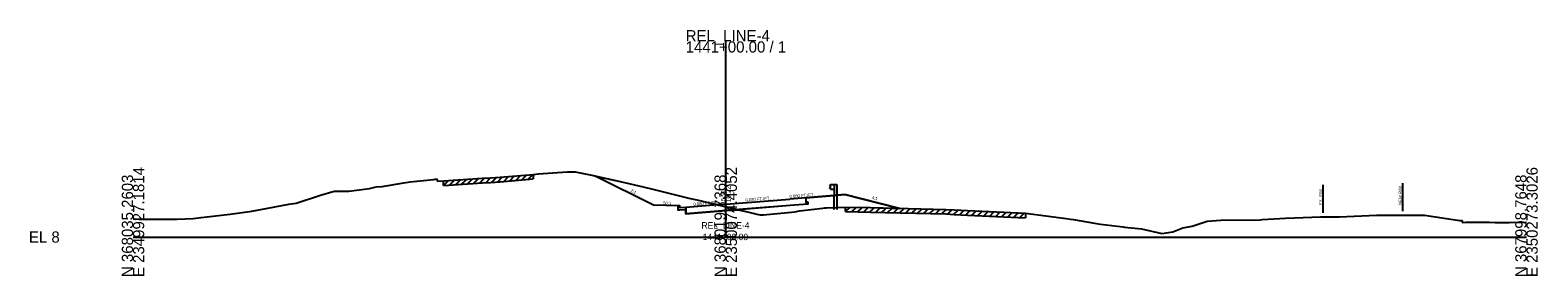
# Model space of a CAD drawing. Extents: x -26 to 2350146, y -10 to 368200.
# Drawn here: x 1974.3 to 2350.9, y 1990.3 to 2051.7 of the extents above; entities that cross this region are included whole.
import ezdxf

# ---------------------------------------------------------------- set-up
doc = ezdxf.new("R2010")
doc.units = 0
for name, color, linetype in [('RD_GPK_XS_Cell', 7, 'Continuous'), ('RD_XS_Base', 7, 'Continuous'), ('RD_XS_CurbBase', 7, 'Continuous'), ('RD_XS_CurbFront', 7, 'Continuous'), ('RD_XS_CurbTop', 7, 'Continuous'), ('RD_XS_Ditch', 7, 'Continuous'), ('RD_XS_EarthShd', 7, 'Continuous'), ('RD_XS_EwShp', 7, 'Continuous'), ('RD_XS_ExGround', 7, 'Continuous'), ('RD_XS_ExPaveRet', 7, 'Continuous'), ('RD_XS_ExRW', 7, 'Continuous'), ('RD_XS_GR', 7, 'Continuous'), ('RD_XS_NewRW', 7, 'Continuous'), ('RD_XS_Pave', 7, 'Continuous'), ('RD_XS_PaveShd', 7, 'Continuous'), ('RD_XS_TieSlope', 7, 'Continuous'), ('RD_XS_TX_Elev_EX', 7, 'Continuous'), ('RD_XS_TX_Elev_PR', 7, 'Continuous'), ('RD_XS_TX_Slope', 7, 'Continuous'), ('RD_XS_TX_Station', 7, 'Continuous'), ('RD_XS_TX_TOC', 7, 'Continuous')]:
    doc.layers.add(name, color=color, linetype=linetype)

msp = doc.modelspace()

# ---------------------------------------------------------------- linework, layer by layer
at = {"layer": 'RD_GPK_XS_Cell'}
for p, q in [((2148.04, 2000), (2148.04, 2048.88)), ((2000, 2000), (2148.04, 2000)), ((2148.04, 2000), (2348.04, 2000))]:
    msp.add_line(p, q, dxfattribs=at)
at = {"layer": 'RD_XS_Base'}
for p, q in [((2164.17, 2007.87), (2148.17, 2006.59)), ((2168.55, 2008.22), (2164.17, 2007.87)), ((2168.05, 2009.82), (2168.05, 2008.68)), ((2168.55, 2008.72), (2168.55, 2008.22)), ((2138.04, 2005.78), (2138.04, 2006.9)), ((2148.17, 2006.59), (2138.04, 2005.78))]:
    msp.add_line(p, q, dxfattribs=at)
at = {"layer": 'RD_XS_CurbBase'}
for p, q in [((2136.04, 2007.82), (2136.04, 2006.82)), ((2168.55, 2008.72), (2168.05, 2008.68)), ((2136.04, 2006.82), (2136.54, 2006.82)), ((2136.54, 2006.82), (2138.04, 2006.9))]:
    msp.add_line(p, q, dxfattribs=at)
at = {"layer": 'RD_XS_CurbFront'}
msp.add_line((2138.04, 2006.9), (2138.04, 2007.4), dxfattribs=at)
at = {"layer": 'RD_XS_CurbTop'}
for p, q in [((2136.54, 2007.82), (2136.04, 2007.82)), ((2136.62, 2007.32), (2136.54, 2007.82)), ((2138.04, 2007.4), (2136.62, 2007.32)), ((2138.04, 2007.42), (2138.04, 2007.4))]:
    msp.add_line(p, q, dxfattribs=at)
at = {"layer": 'RD_XS_Ditch'}
msp.add_line((2177.79, 2010.6), (2191.5, 2007.17), dxfattribs=at)
at = {"layer": 'RD_XS_EarthShd'}
for p, q in [((2136.04, 2007.82), (2130.04, 2007.94)), ((2168.05, 2009.82), (2174.04, 2010.3))]:
    msp.add_line(p, q, dxfattribs=at)
at = {"layer": 'RD_XS_EwShp'}
for points in [[(2145.92, 2008.05), (2138.04, 2007.4), (2136.62, 2007.32), (2136.54, 2007.82), (2136.04, 2007.82), (2130.04, 2007.94), (2115.42, 2015.24), (2121.65, 2013.9), (2127.43, 2012.5), (2130.13, 2011.9), (2134.8, 2010.67), (2138.79, 2009.71), (2141.53, 2009.1), (2145.31, 2008.19)], [(2138.04, 2007.4), (2136.62, 2007.32), (2136.54, 2007.82), (2136.04, 2007.82), (2136.04, 2006.82), (2136.54, 2006.82), (2138.04, 2006.9)], [(2145.92, 2008.05), (2138.04, 2007.4), (2138.04, 2006.9), (2138.04, 2005.78), (2148.17, 2006.59), (2151.14, 2006.83), (2148.04, 2007.55)], [(2151.14, 2006.83), (2153.45, 2006.29), (2155.79, 2005.7), (2156.65, 2005.52), (2157.47, 2005.52), (2165.32, 2006.32), (2166.44, 2006.51), (2172.26, 2007.21), (2172.79, 2007.29), (2173.2, 2007.3), (2177.97, 2007.49), (2184.18, 2007.34), (2191.5, 2007.17), (2177.79, 2010.6), (2174.04, 2010.3), (2168.05, 2009.82), (2168.05, 2008.68), (2168.55, 2008.72), (2168.55, 2008.22), (2164.17, 2007.87)]]:
    msp.add_lwpolyline(points, close=True, dxfattribs=at)
at = {"layer": 'RD_XS_ExGround'}
msp.add_lwpolyline([(2000, 2004.54), (2001.45, 2004.5), (2002.57, 2004.5), (2010.99, 2004.48), (2015.02, 2004.6), (2016.98, 2004.87), (2023.54, 2005.63), (2024.25, 2005.7), (2029.69, 2006.5), (2035.02, 2007.47), (2038.95, 2008.19), (2040.77, 2008.48), (2046.8, 2010.43), (2050.28, 2011.44), (2053.94, 2011.45), (2059.04, 2012.16), (2060.75, 2012.51), (2062.2, 2012.66), (2067.63, 2013.53), (2069.2, 2013.78), (2075.05, 2014.39), (2075.42, 2014.42), (2075.92, 2014.42), (2076.08, 2013.93), (2077.58, 2014.01), (2087.32, 2014.67), (2089.26, 2014.8), (2091.68, 2014.98), (2099.91, 2015.65), (2101.24, 2015.82), (2108.44, 2016.29), (2110.41, 2016.27), (2114.58, 2015.43), (2121.65, 2013.9), (2127.43, 2012.5), (2130.13, 2011.9), (2134.8, 2010.67), (2138.79, 2009.71), (2141.53, 2009.1), (2145.31, 2008.19), (2148.04, 2007.55), (2153.45, 2006.29), (2155.79, 2005.7), (2156.65, 2005.52), (2157.47, 2005.52), (2165.32, 2006.32), (2166.44, 2006.51), (2172.26, 2007.21), (2172.79, 2007.29), (2173.2, 2007.3), (2177.97, 2007.49), (2184.18, 2007.34), (2203.02, 2006.91), (2205.09, 2006.8), (2208.44, 2006.64), (2222.92, 2005.97), (2233.11, 2004.64), (2234.19, 2004.5), (2234.92, 2004.4), (2240.13, 2003.47), (2241.64, 2003.24), (2247.3, 2002.53), (2247.67, 2002.5), (2251.85, 2002.07), (2256.93, 2000.92), (2259.67, 2001.33), (2262.21, 2002.33), (2264.52, 2002.71), (2268.28, 2003.98), (2271.69, 2004.2), (2281.55, 2004.3), (2282.04, 2004.36), (2287.85, 2004.73), (2290.08, 2004.77), (2296.63, 2005.07), (2301.33, 2005.05), (2310.62, 2005.48), (2312.02, 2005.44), (2314.31, 2005.45), (2322.53, 2005.44), (2330.81, 2004.25), (2331.34, 2004.12), (2331.88, 2004.12), (2332.05, 2003.62), (2332.87, 2003.7), (2335.31, 2003.7), (2336.95, 2003.69), (2338.81, 2003.68), (2340.2, 2003.67), (2343.69, 2003.63), (2348.04, 2003.75)], dxfattribs=at)
at = {"layer": 'RD_XS_ExPaveRet'}
for p, q in [((2086.58, 2013.48), (2087.8, 2014.7)), ((2088.08, 2013.58), (2089.3, 2014.8)), ((2089.58, 2013.68), (2090.81, 2014.91)), ((2091.08, 2013.79), (2092.32, 2015.03)), ((2092.58, 2013.91), (2093.82, 2015.15)), ((2094.08, 2014.03), (2095.32, 2015.27)), ((2095.58, 2014.15), (2096.82, 2015.4)), ((2097.08, 2014.27), (2098.32, 2015.52)), ((2098.58, 2014.4), (2099.82, 2015.64)), ((2099.91, 2015.65), (2099.91, 2014.5)), ((2077.58, 2012.86), (2078.81, 2014.09)), ((2077.58, 2012.86), (2077.58, 2014.01)), ((2077.58, 2012.86), (2087.32, 2013.53)), ((2079.08, 2012.97), (2080.31, 2014.19)), ((2080.58, 2013.07), (2081.81, 2014.3)), ((2082.08, 2013.17), (2083.31, 2014.4)), ((2083.58, 2013.27), (2084.81, 2014.5)), ((2085.08, 2013.38), (2086.31, 2014.6)), ((2087.32, 2013.53), (2089.26, 2013.66)), ((2089.26, 2013.66), (2091.68, 2013.83)), ((2091.68, 2013.83), (2099.91, 2014.5)), ((2177.97, 2006.34), (2177.97, 2007.49)), ((2177.97, 2006.34), (2179.08, 2007.46)), ((2179.47, 2006.31), (2180.58, 2007.42)), ((2180.97, 2006.27), (2182.08, 2007.39)), ((2182.47, 2006.24), (2183.58, 2007.35)), ((2183.97, 2006.2), (2185.08, 2007.32)), ((2185.47, 2006.17), (2186.58, 2007.29)), ((2186.97, 2006.13), (2188.08, 2007.25)), ((2188.47, 2006.1), (2189.58, 2007.22)), ((2189.97, 2006.07), (2191.08, 2007.18)), ((2191.47, 2006.03), (2192.58, 2007.15)), ((2177.97, 2006.34), (2184.18, 2006.2)), ((2184.18, 2006.2), (2203.02, 2005.77)), ((2192.97, 2006), (2194.08, 2007.11)), ((2194.47, 2005.96), (2195.58, 2007.08)), ((2195.97, 2005.93), (2197.08, 2007.04)), ((2197.47, 2005.89), (2198.58, 2007.01)), ((2198.97, 2005.86), (2200.08, 2006.98)), ((2200.47, 2005.82), (2201.58, 2006.94)), ((2201.97, 2005.79), (2203.08, 2006.91)), ((2203.02, 2005.77), (2205.09, 2005.65)), ((2203.47, 2005.74), (2204.55, 2006.83)), ((2204.97, 2005.66), (2206.06, 2006.75)), ((2205.09, 2005.65), (2208.44, 2005.5)), ((2206.47, 2005.59), (2207.56, 2006.68)), ((2207.97, 2005.52), (2209.06, 2006.62)), ((2208.44, 2005.5), (2222.92, 2004.83)), ((2209.47, 2005.45), (2210.56, 2006.55)), ((2210.97, 2005.38), (2212.06, 2006.48)), ((2212.47, 2005.31), (2213.56, 2006.41)), ((2213.97, 2005.24), (2215.06, 2006.34)), ((2215.47, 2005.17), (2216.56, 2006.27)), ((2216.97, 2005.11), (2218.06, 2006.2)), ((2218.47, 2005.04), (2219.56, 2006.13)), ((2219.97, 2004.97), (2221.06, 2006.06)), ((2221.47, 2004.9), (2222.56, 2005.99)), ((2222.92, 2005.97), (2222.92, 2004.83))]:
    msp.add_line(p, q, dxfattribs=at)
at = {"layer": 'RD_XS_ExRW'}
msp.add_line((2297.3, 2006.07), (2297.3, 2013.07), dxfattribs=at)
at = {"layer": 'RD_XS_GR'}
for p, q in [((2174.2, 2013.05), (2174.03, 2012.85)), ((2174.03, 2012.85), (2174.03, 2012.8)), ((2174.03, 2012.8), (2174.2, 2012.6)), ((2174.03, 2012.27), (2174.2, 2012.47)), ((2174.03, 2012.22), (2174.03, 2012.27)), ((2174.2, 2012.02), (2174.03, 2012.22)), ((2174.2, 2013.12), (2175.12, 2013.12)), ((2174.2, 2011.95), (2174.2, 2013.12)), ((2174.2, 2011.95), (2175.12, 2011.95)), ((2175.12, 2013.12), (2175.78, 2013.12)), ((2175.12, 2013.12), (2175.12, 2010.37)), ((2175.78, 2013.12), (2175.78, 2010.32)), ((2175.12, 2006.9), (2175.12, 2010.37)), ((2175.78, 2010.32), (2175.78, 2006.9))]:
    msp.add_line(p, q, dxfattribs=at)
at = {"layer": 'RD_XS_NewRW'}
msp.add_line((2317.16, 2006.45), (2317.16, 2013.45), dxfattribs=at)
at = {"layer": 'RD_XS_Pave'}
for q in [(2138.04, 2007.42), (2164.04, 2009.5)]:
    msp.add_line((2148.04, 2008.22), q, dxfattribs=at)
at = {"layer": 'RD_XS_PaveShd'}
msp.add_line((2168.05, 2009.82), (2164.04, 2009.5), dxfattribs=at)
at = {"layer": 'RD_XS_TieSlope'}
for p, q in [((2130.04, 2007.94), (2115.42, 2015.24)), ((2174.04, 2010.3), (2177.79, 2010.6))]:
    msp.add_line(p, q, dxfattribs=at)

# ---------------------------------------------------------------- texts
at = {"layer": 'RD_GPK_XS_Cell'}
for s, p in [('1441+00.00 / 1', (2138.04, 2046.08)), ('REL_LINE-4', (2138.04, 2048.88)), ('EL 8', (1974, 1998.6))]:
    msp.add_text(s, height=2.8, dxfattribs=at).set_placement(p)
for s, p in [('N 368035.2603', (2000, 1990)), ('E 2349927.1814', (2002.8, 1990)), ('N 368019.7368', (2148.04, 1990)), ('E 2350074.4052', (2150.84, 1990)), ('N 367998.7648', (2348.04, 1990)), ('E 2350273.3026', (2350.84, 1990))]:
    msp.add_text(s, height=2.8, rotation=90, dxfattribs=at).set_placement(p)
at = {"layer": 'RD_XS_ExRW'}
msp.add_text('EX. R/W ', height=0.75, rotation=90, dxfattribs=at).set_placement((2297.02, 2008.02))
at = {"layer": 'RD_XS_NewRW'}
msp.add_text('NEW R/W ', height=0.75, rotation=90, dxfattribs=at).set_placement((2316.87, 2008.03))
at = {"layer": 'RD_XS_TX_Elev_EX'}
msp.add_text('15.55', height=1, rotation=90, dxfattribs=at).set_placement((2147.88, 2008.18))
at = {"layer": 'RD_XS_TX_Elev_PR'}
msp.add_text(' 16.22', height=1.2, rotation=90, dxfattribs=at).set_placement((2149.24, 2008.22))
at = {"layer": 'RD_XS_TX_Slope'}
for s, rotation, p in [('2:1', 333.4349, (2124.2, 2011.38)), ('0.080 FT./FT.', 4.5739, (2164, 2009.75)), ('50:1', 358.8542, (2132.4, 2008.12)), ('0.080 FT./FT.', 4.5739, (2140, 2007.83)), ('0.080 FT./FT.', 4.5739, (2153, 2008.87)), ('4:1', 345.9638, (2184.45, 2009.54))]:
    msp.add_text(s, height=0.75, rotation=rotation, dxfattribs=at).set_placement(p)
at = {"layer": 'RD_XS_TX_Station'}
for s, p in [('REL_LINE-4', (2141.97, 2002.12)), ('1441+00.00', (2142.27, 1999.22))]:
    msp.add_text(s, height=1.6, dxfattribs=at).set_placement(p)
at = {"layer": 'RD_XS_TX_TOC'}
msp.add_text('TOCLT', height=0.05, dxfattribs=at).set_placement((2136.59, 2007.77))

doc.saveas('drawing.dxf')
